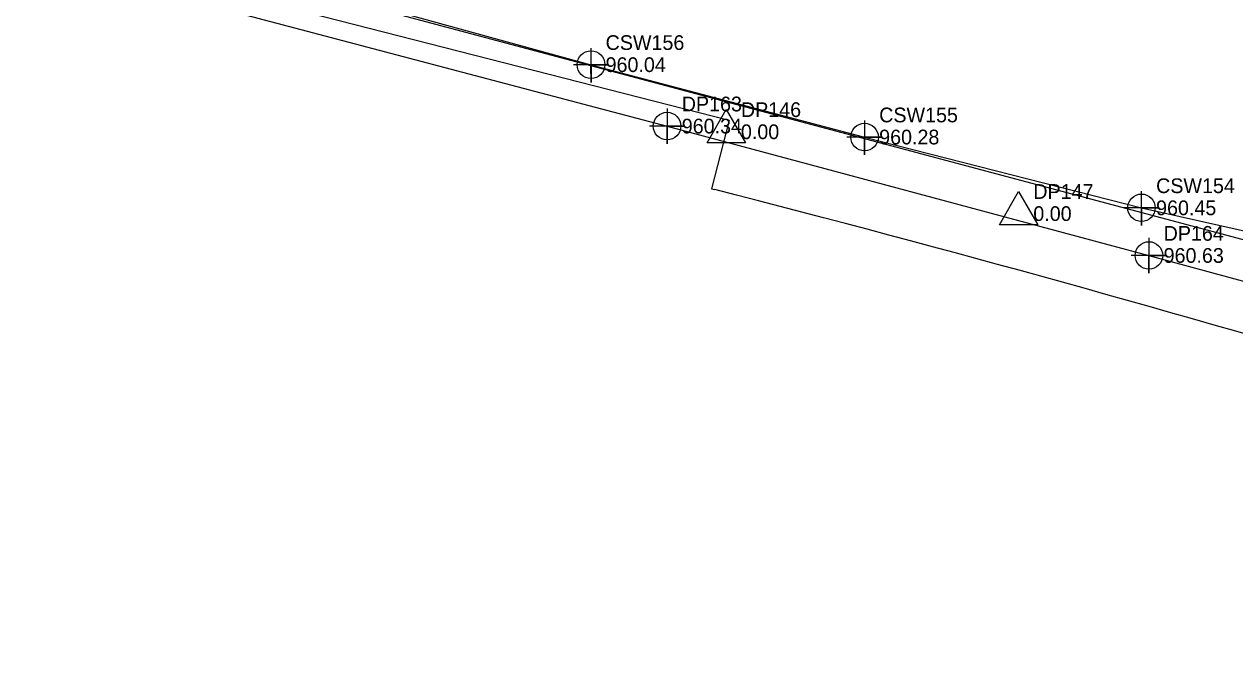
# Model space of a CAD drawing. Extents: x 1182322 to 1186765, y 572295 to 575411.
# Drawn here: x 1183226.6 to 1183432.3, y 574148.9 to 574259 of the extents above; entities that cross this region are included whole.
import ezdxf

# ---------------------------------------------------------------- set-up
doc = ezdxf.new("R2010")
doc.units = 0
for name, color, linetype in [('COGO Default Chain', 7, 'Continuous'), ('Exist Horizontal Alignment', 7, 'Continuous'), ('Exist Other Culture Fence Line', 7, 'Continuous'), ('Exist Other Culture Fence Line Cogo Elevation', 7, 'Continuous'), ('Exist Other Culture Fence Line Cogo Number', 7, 'Continuous'), ('Exist Other Culture Fence Line Cogo Point CELL', 7, 'Continuous'), ('Exist Right of Way Line', 7, 'Continuous'), ('Exist Right of Way Monument CELL', 7, 'Continuous'), ('Exist Right of Way Monument Cogo Elevation', 7, 'Continuous'), ('Exist Right of Way Monument Cogo Number', 7, 'Continuous'), ('Exist Utilities Telephone UG Conduit SUE LOS B', 7, 'Continuous'), ('Exist Utilities Telephone UG Conduit SUE LOS B Cogo Elevation', 7, 'Continuous'), ('Exist Utilities Telephone UG Conduit SUE LOS B Cogo Number', 7, 'Continuous'), ('Exist Utilities Telephone UG Conduit SUE LOS B Cogo Point CELL', 7, 'Continuous'), ('Sheet Layout Plan Border', 7, 'Continuous')]:
    doc.layers.add(name, color=color, linetype=linetype)

msp = doc.modelspace()

# ---------------------------------------------------------------- linework, layer by layer
at = {"layer": 'COGO Default Chain'}
msp.add_arc((1182574.75, 571226.37), 3201.45, 68.49303, 75.64052, dxfattribs=at)
at = {"layer": 'Exist Horizontal Alignment'}
msp.add_arc((1182574.75, 571226.37), 3201.45, 68.49303, 75.64052, dxfattribs=at)
at = {"layer": 'Exist Other Culture Fence Line'}
msp.add_lwpolyline([(1182431.26, 574477.6), (1182493.19, 574461.53), (1182576.37, 574440.23), (1182660.35, 574418.61), (1182745.71, 574396.94), (1182831.35, 574374.93), (1182917.06, 574353.23), (1182998.89, 574331.88), (1183080.06, 574310.08), (1183166.11, 574287.18), (1183252.15, 574263.83), (1183335.82, 574241.7), (1183417.69, 574219.73), (1183503.47, 574196.43), (1183592.65, 574167.54), (1183679.28, 574135.7), (1183764.86, 574099.44), (1183841.01, 574057.63), (1183931.32, 574004.09)], dxfattribs=at)
at = {"layer": 'Exist Other Culture Fence Line Cogo Point CELL'}
for points in [[(1183335.82, 574244.7), (1183335.82, 574238.7), (1183335.82, 574241.7), (1183338.82, 574241.7), (1183332.82, 574241.7)], [(1183417.69, 574222.73), (1183417.69, 574216.73), (1183417.69, 574219.73), (1183420.69, 574219.73), (1183414.69, 574219.73)]]:
    msp.add_lwpolyline(points, dxfattribs=at)
for centre in [(1183335.82, 574241.7), (1183417.69, 574219.73)]:
    msp.add_circle(centre, 2.34, dxfattribs=at)
at = {"layer": 'Exist Right of Way Line'}
for p, q in [((1182496.14, 574460.35), (1183346.37, 574242.68)), ((1183346.37, 574242.68), (1183343.39, 574231.06)), ((1183343.39, 574231.06), (1183343.92, 574230.92))]:
    msp.add_line(p, q, dxfattribs=at)
msp.add_arc((1182574.75, 571226.37), 3101.45, 71.1212, 75.64052, dxfattribs=at)
at = {"layer": 'Exist Right of Way Monument CELL'}
for p, q in [((1183345.87, 574240.74), (1183345.87, 574240.74)), ((1183395.55, 574226.84), (1183395.55, 574226.84))]:
    msp.add_line(p, q, dxfattribs=at)
for points in [[(1183342.62, 574238.85), (1183345.87, 574244.49), (1183349.12, 574238.85)], [(1183392.3, 574224.95), (1183395.55, 574230.59), (1183398.8, 574224.95)]]:
    msp.add_lwpolyline(points, close=True, dxfattribs=at)
at = {"layer": 'Exist Utilities Telephone UG Conduit SUE LOS B'}
msp.add_lwpolyline([(1183184.2, 574290.24), (1183230.46, 574277.8), (1183276.74, 574264.86), (1183322.88, 574252.13), (1183369.36, 574239.84), (1183416.41, 574227.82), (1183461.9, 574217.61), (1183507.97, 574205.1), (1183555.78, 574190.97), (1183600.29, 574174.7), (1183642.38, 574158.78), (1183685.83, 574141.54), (1183729.44, 574124.53), (1183772.61, 574105.48), (1183815.48, 574084.72), (1183856.9, 574064.89), (1183910.26, 574040.72), (1183938.65, 574025.64), (1184017.13, 573974.93), (1184056.25, 573949.51), (1184095.95, 573918.75), (1184120.25, 573896.12), (1184153.18, 573876.37), (1184177.6, 573863.32)], dxfattribs=at)
at = {"layer": 'Exist Utilities Telephone UG Conduit SUE LOS B Cogo Point CELL'}
for points in [[(1183322.87, 574254.95), (1183322.9, 574249.13), (1183322.88, 574252.13), (1183325.9, 574252.13), (1183319.9, 574252.13)], [(1183369.34, 574242.65), (1183369.38, 574236.84), (1183369.36, 574239.84), (1183372.38, 574239.84), (1183366.38, 574239.84)], [(1183416.39, 574230.63), (1183416.42, 574224.82), (1183416.41, 574227.82), (1183419.42, 574227.82), (1183413.42, 574227.82)]]:
    msp.add_lwpolyline(points, dxfattribs=at)
for centre in [(1183322.9, 574252.13), (1183369.38, 574239.84), (1183416.42, 574227.82)]:
    msp.add_circle(centre, 2.34, dxfattribs=at)
at = {"layer": 'Sheet Layout Plan Border'}
msp.add_line((1183012.24, 574334.8), (1183524.74, 574198.18), dxfattribs=at)

# ---------------------------------------------------------------- texts
at = {"layer": 'Exist Other Culture Fence Line Cogo Elevation'}
for s, p in [('960.34', (1183338.32, 574240.45)), ('960.63', (1183420.19, 574218.48))]:
    msp.add_text(s, height=2.5, dxfattribs=at).set_placement(p)
at = {"layer": 'Exist Other Culture Fence Line Cogo Number'}
for s, p in [('DP163', (1183338.32, 574244.2)), ('DP164', (1183420.19, 574222.23))]:
    msp.add_text(s, height=2.5, dxfattribs=at).set_placement(p)
at = {"layer": 'Exist Right of Way Monument Cogo Elevation'}
for p in [(1183348.37, 574239.49), (1183398.05, 574225.59)]:
    msp.add_text('0.00', height=2.5, dxfattribs=at).set_placement(p)
at = {"layer": 'Exist Right of Way Monument Cogo Number'}
for s, p in [('DP146', (1183348.37, 574243.24)), ('DP147', (1183398.05, 574229.34))]:
    msp.add_text(s, height=2.5, dxfattribs=at).set_placement(p)
at = {"layer": 'Exist Utilities Telephone UG Conduit SUE LOS B Cogo Elevation'}
for s, p in [('960.04', (1183325.38, 574250.88)), ('960.28', (1183371.86, 574238.59)), ('960.45', (1183418.91, 574226.57))]:
    msp.add_text(s, height=2.5, dxfattribs=at).set_placement(p)
at = {"layer": 'Exist Utilities Telephone UG Conduit SUE LOS B Cogo Number'}
for s, p in [('CSW156', (1183325.38, 574254.63)), ('CSW155', (1183371.86, 574242.34)), ('CSW154', (1183418.91, 574230.32))]:
    msp.add_text(s, height=2.5, dxfattribs=at).set_placement(p)

doc.saveas('drawing.dxf')
